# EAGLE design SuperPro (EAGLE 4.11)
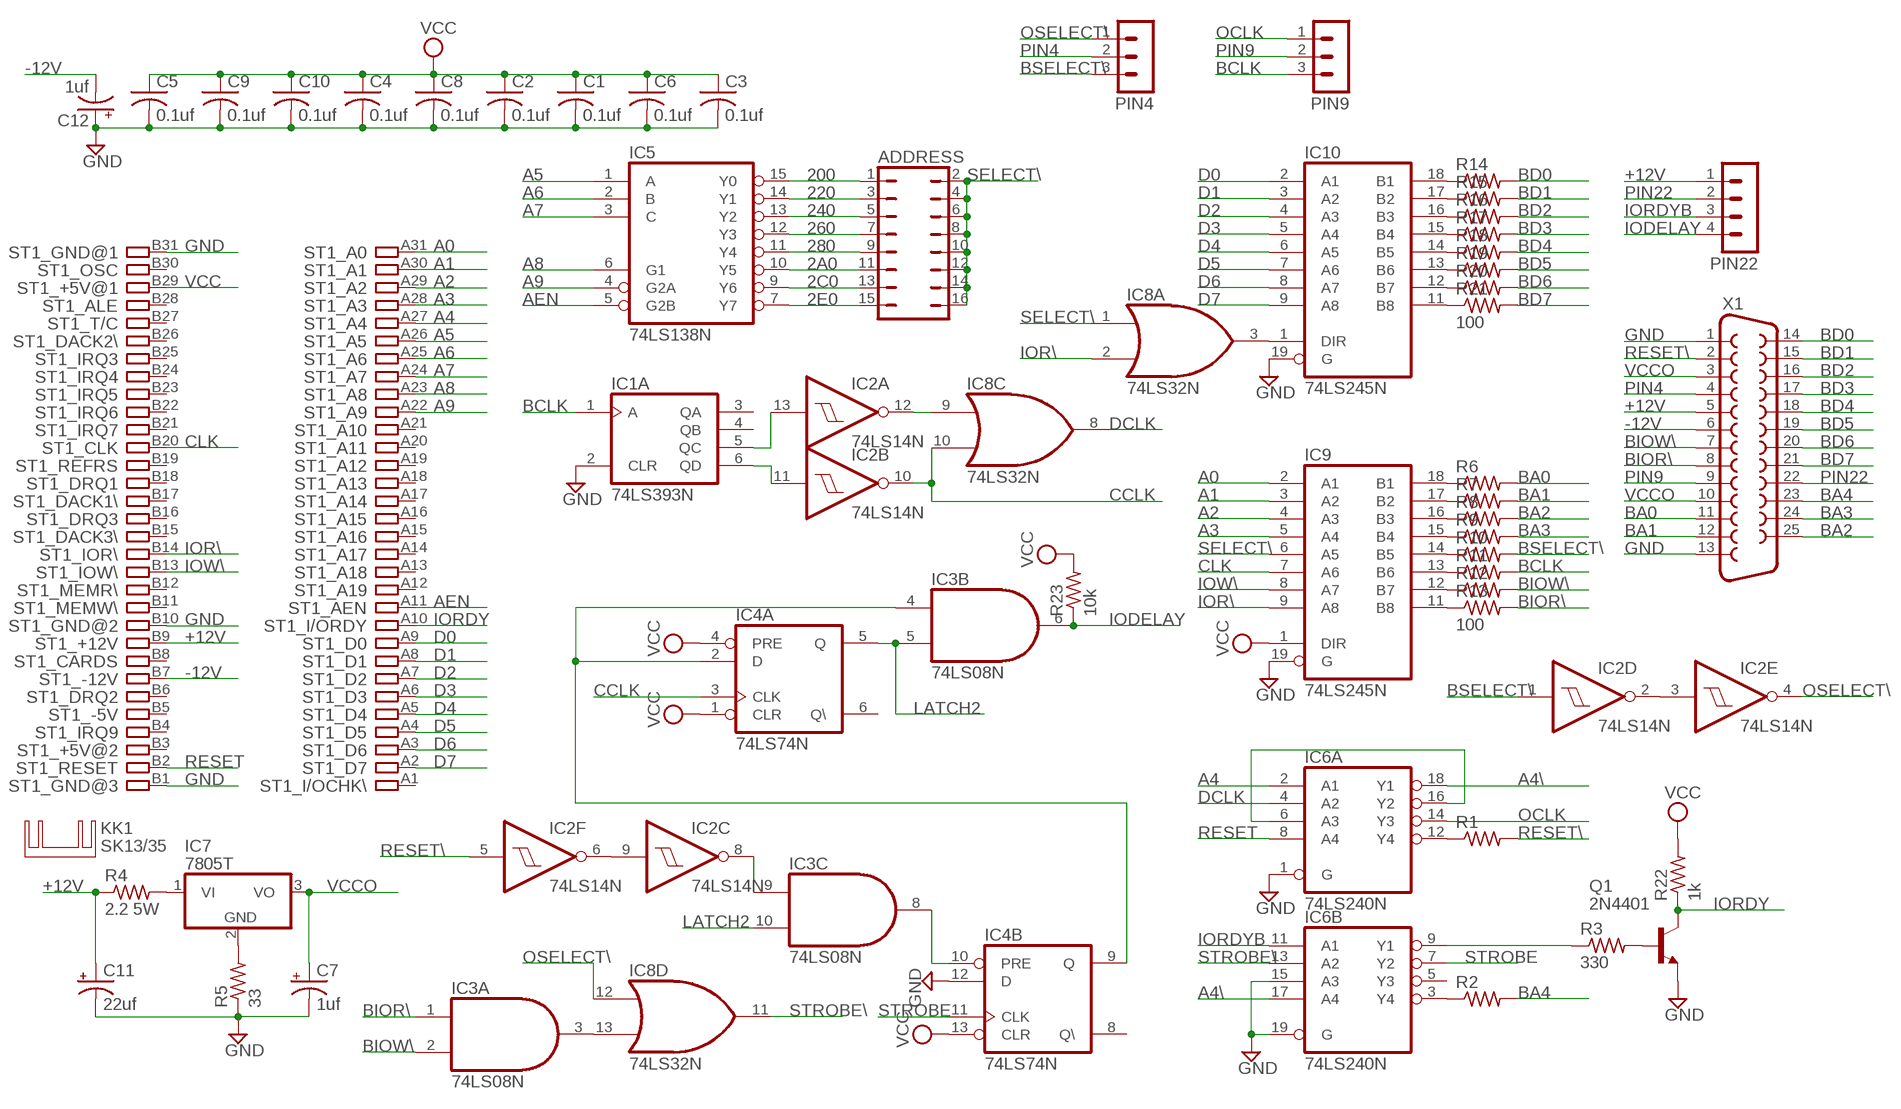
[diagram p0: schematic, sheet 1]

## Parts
ADDRESS  JP8Q  [JP8Q]
C1  0.1uf  C-US050-025X075  [C050-025X075]
C2  0.1uf  C-US050-025X075  [C050-025X075]
C3  0.1uf  C-US050-025X075  [C050-025X075]
C4  0.1uf  C-US050-025X075  [C050-025X075]
C5  0.1uf  C-US050-025X075  [C050-025X075]
C6  0.1uf  C-US050-025X075  [C050-025X075]
C7  1uf  CPOL-USE5-10.5  [E5-10,5]
C8  0.1uf  C-US050-025X075  [C050-025X075]
C9  0.1uf  C-US050-025X075  [C050-025X075]
C10  0.1uf  C-US050-025X075  [C050-025X075]
C11  22uf  CPOL-USE5-10.5  [E5-10,5]
C12  1uf  CPOL-USE5-10.5  [E5-10,5]
IC1  74LS393N  [DIL14]
IC2  74LS14N  [DIL14]
IC3  74LS08N  [DIL14]
IC4  74LS74N  [DIL14]
IC5  74LS138N  [DIL16]
IC6  74LS240N  [DIL20]
IC7  7805T  [TO220H]
IC8  74LS32N  [DIL14]
IC9  74LS245N  [DIL20]
IC10  74LS245N  [DIL20]
KK1  SK13/35  [SK13/35]
PIN4  MA03-1  [MA03-1]
PIN9  MA03-1  [MA03-1]
PIN22  MA04-1  [MA04-1]
Q1  2N4401  2N4416  [TO92]
R1  R-US_0207/10  [0207/10]
R2  R-US_0207/10  [0207/10]
R3  330  R-US_0207/10  [0207/10]
R4  2.2 5W  R-US_0922/22  [0922/22]
R5  33  R-US_0207/10  [0207/10]
R6  R-US_0207/10  [0207/10]
R7  R-US_0207/10  [0207/10]
R8  R-US_0207/10  [0207/10]
R9  R-US_0207/10  [0207/10]
R10  R-US_0207/10  [0207/10]
R11  R-US_0207/10  [0207/10]
R12  R-US_0207/10  [0207/10]
R13  100  R-US_0207/10  [0207/10]
R14  R-US_0207/10  [0207/10]
R15  R-US_0207/10  [0207/10]
R16  R-US_0207/10  [0207/10]
R17  R-US_0207/10  [0207/10]
R18  R-US_0207/10  [0207/10]
R19  R-US_0207/10  [0207/10]
R20  R-US_0207/10  [0207/10]
R21  100  R-US_0207/10  [0207/10]
R22  1k  R-US_0207/10  [0207/10]
R23  10k  R-US_0207/10  [0207/10]
ST1  IBM8BIT  [IBM8BIT]
X1  F25H  [F25H]

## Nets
2A0: ADDRESS.11 IC5.10(Y5)
2C0: ADDRESS.13 IC5.9(Y6)
2E0: ADDRESS.15 IC5.7(Y7)
200: ADDRESS.1 IC5.15(Y0)
220: ADDRESS.3 IC5.14(Y1)
240: ADDRESS.5 IC5.13(Y2)
260: ADDRESS.7 IC5.12(Y3)
280: ADDRESS.9 IC5.11(Y4)
+12V [Power]: C11.+ PIN22.1 R4.1 ST1.B9 X1.5
-12V [Power]: C12.- ST1.B7 X1.6
A0: IC9.2(A1) ST1.A31
A1: IC9.3(A2) ST1.A30
A2: IC9.4(A3) ST1.A29
A3: IC9.5(A4) ST1.A28
A4: IC6.2(A:A1) ST1.A27
A4\: IC6.17(B:A4) IC6.18(A:Y1)
A5: IC5.1(A) ST1.A26
A6: IC5.2(B) ST1.A25
A7: IC5.3(C) ST1.A24
A8: IC5.6(G1) ST1.A23
A9: IC5.4(G2A) ST1.A22
AEN: IC5.5(G2B) ST1.A11
BA0: R6.2 X1.11
BA1: R7.2 X1.12
BA2: R8.2 X1.25
BA3: R9.2 X1.24
BA4: R2.2 X1.23
BCLK: IC1.1(A:A) PIN9.3 R11.2
BD0: R14.2 X1.14
BD1: R15.2 X1.15
BD2: R16.2 X1.16
BD3: R17.2 X1.17
BD4: R18.2 X1.18
BD5: R19.2 X1.19
BD6: R20.2 X1.20
BD7: R21.2 X1.21
BIOR\: IC3.1(A:I0) R13.2 X1.8
BIOW\: IC3.2(A:I1) R12.2 X1.7
BSELECT\: IC2.1(D:I) PIN4.3 R10.2
CCLK: IC2.10(B:O) IC4.3(A:CLK) IC8.10(C:I1)
CLK: IC9.7(A6) ST1.B20
D0: IC10.2(A1) ST1.A9
D1: IC10.3(A2) ST1.A8
D2: IC10.4(A3) ST1.A7
D3: IC10.5(A4) ST1.A6
D4: IC10.6(A5) ST1.A5
D5: IC10.7(A6) ST1.A4
D6: IC10.8(A7) ST1.A3
D7: IC10.9(A8) ST1.A2
DCLK: IC6.4(A:A2) IC8.8(C:O)
GND [Power]: C1.2 C2.2 C3.2 C4.2 C5.2 C6.2 C7.- C8.2 C9.2 C10.2 C11.- C12.+ IC1.2(A:CLR) IC4.12(B:D) IC6.1(A:G) IC6.15(B:A3) IC6.19(B:G) IC9.19(G) IC10.19(G) Q1.3(E) R5.1 ST1.B1 ST1.B10 ST1.B31 X1.1 X1.13
IODELAY: IC3.6(B:O) PIN22.4 R23.1
IOR\: IC8.2(A:I1) IC9.9(A8) ST1.B14
IORDY: Q1.1(C) R22.1 ST1.A10
IORDYB: IC6.11(B:A1) PIN22.3
IOW\: IC9.8(A7) ST1.B13
LATCH2: IC3.5(B:I1) IC3.10(C:I1) IC4.5(A:Q)
N$1: IC8.3(A:O) IC10.1(DIR)
N$2 [Power]: IC7.2(GND) R5.2
N$3: IC10.13(B6) R19.1
N$4: IC10.17(B2) R15.1
N$5: IC10.16(B3) R16.1
N$6: IC10.15(B4) R17.1
N$7: IC10.14(B5) R18.1
N$8: IC10.12(B7) R20.1
N$9: IC10.11(B8) R21.1
N$10: IC10.18(B1) R14.1
N$11: IC9.18(B1) R6.1
N$12: IC9.17(B2) R7.1
N$13: IC9.16(B3) R8.1
N$14: IC9.15(B4) R9.1
N$15: IC9.14(B5) R10.1
N$16: IC9.13(B6) R11.1
N$17: IC9.12(B7) R12.1
N$18: IC9.11(B8) R13.1
N$19: IC6.12(A:Y4) R1.1
N$20: IC2.6(F:O) IC2.9(C:I)
N$21: IC2.2(D:O) IC2.3(E:I)
N$22: IC1.6(A:QD) IC2.11(B:I)
N$23: IC6.3(B:Y4) R2.1
N$24: IC1.5(A:QC) IC2.13(A:I)
N$25 [Power]: IC7.1(VI) R4.2
N$26: IC2.12(A:O) IC8.9(C:I0)
N$28: IC6.6(A:A3) IC6.16(A:Y2)
N$29: IC3.3(A:O) IC8.13(D:I1)
N$30: IC3.4(B:I0) IC4.2(A:D) IC4.9(B:Q)
N$32: IC6.9(B:Y1) R3.1
N$33: IC3.8(C:O) IC4.10(B:PRE)
N$34: IC2.8(C:O) IC3.9(C:I0)
N$37: Q1.2(B) R3.2
OCLK: IC6.14(A:Y3) PIN9.1
OSELECT\: IC2.4(E:O) IC8.12(D:I0) PIN4.1
PIN4: PIN4.2 X1.4
PIN9: PIN9.2 X1.9
PIN22 [Power]: PIN22.2 X1.22
RESET: IC6.8(A:A4) ST1.B2
RESET\: IC2.5(F:I) R1.2 X1.2
SELECT\: ADDRESS.2 ADDRESS.4 ADDRESS.6 ADDRESS.8 ADDRESS.10 ADDRESS.12 ADDRESS.14 ADDRESS.16 IC8.1(A:I0) IC9.6(A5)
STROBE: IC4.11(B:CLK) IC6.7(B:Y2)
STROBE\: IC6.13(B:A2) IC8.11(D:O)
VCC [Power]: C1.1 C2.1 C3.1 C4.1 C5.1 C6.1 C8.1 C9.1 C10.1 IC4.1(A:CLR) IC4.4(A:PRE) IC4.13(B:CLR) IC9.1(DIR) R22.2 R23.2 ST1.B29
VCCO [Power]: C7.+ IC7.3(VO) X1.3 X1.10
Unconnected: IC1.3(A:QA) IC1.4(A:QB) IC1.8(B:QD) IC1.9(B:QC) IC1.10(B:QB) IC1.11(B:QA) IC1.12(B:CLR) IC1.13(B:A) IC3.11(D:O) IC3.12(D:I0) IC3.13(D:I1) IC4.6(A:Q\) IC4.8(B:Q\) IC6.5(B:Y3) IC8.4(B:I0) IC8.5(B:I1) IC8.6(B:O) ST1.A1 ST1.A12 ST1.A13 ST1.A14 ST1.A15 ST1.A16 ST1.A17 ST1.A18 ST1.A19 ST1.A20 ST1.A21 ST1.B3 ST1.B4 ST1.B5 ST1.B6 ST1.B8 ST1.B11 ST1.B12 ST1.B15 ST1.B16 ST1.B17 ST1.B18 ST1.B19 ST1.B21 ST1.B22 ST1.B23 ST1.B24 ST1.B25 ST1.B26 ST1.B27 ST1.B28 ST1.B30

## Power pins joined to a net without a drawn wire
GND: IC1.7(P:GND) IC2.7(P:GND) IC3.7(P:GND) IC4.7(P:GND) IC5.8(GND) IC6.10(P:GND) IC8.7(P:GND) IC9.10(GND) IC10.10(GND)
VCC: IC1.14(P:VCC) IC2.14(P:VCC) IC3.14(P:VCC) IC4.14(P:VCC) IC5.16(VCC) IC6.20(P:VCC) IC8.14(P:VCC) IC9.20(VCC) IC10.20(VCC)

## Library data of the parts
ADDRESS = jumper:JP8Q: JUMPER
C1-C6 C8-C10 = rcl:C-US: CAPACITOR, American symbol
C7 C11 C12 = rcl:CPOL-US: POLARIZED CAPACITOR, American symbol
IC1 = 74xx-us:74*393: Dual 4-bit decade and binary COUNTER
IC2 = 74xx-us:74*14: Hex schmitt trigger INVERTER
IC3 = 74xx-us:74*08: Quad 2-input AND gate
IC4 = 74xx-us:74*74: Dual D type positive edge triggered FLIP FLOP, preset and clear
IC5 = 74xx-us:74*138: 3-line to 8-line DECODER/DEMULTIPLEXER
IC6 = 74xx-us:74*240: Octal BUFFER and LINE DRIVER, 3-state
IC7 = linear:78*: Positive VOLTAGE REGULATOR
IC8 = 74xx-us:74*32: Quad 2-input OR gate
IC9 IC10 = 74xx-us:74*245: Octal BUS TRANSCEIVER, 3-state
KK1 = heatsink:SK13/35: HEATSINK
PIN4 PIN9 = con-lstb:MA03-1: PIN HEADER
PIN22 = con-lstb:MA04-1: PIN HEADER
Q1 = transistor-npn:2N4416: NPN Transistor
R1-R23 = rcl:R-US_: RESISTOR, American symbol
ST1 = con-pc:IBM8BIT: 8-bit CARD IBM/PC-AT
X1 = con-subd:F25: SUB-D

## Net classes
1 Power: width 0.762 mm, drill 0.254 mm

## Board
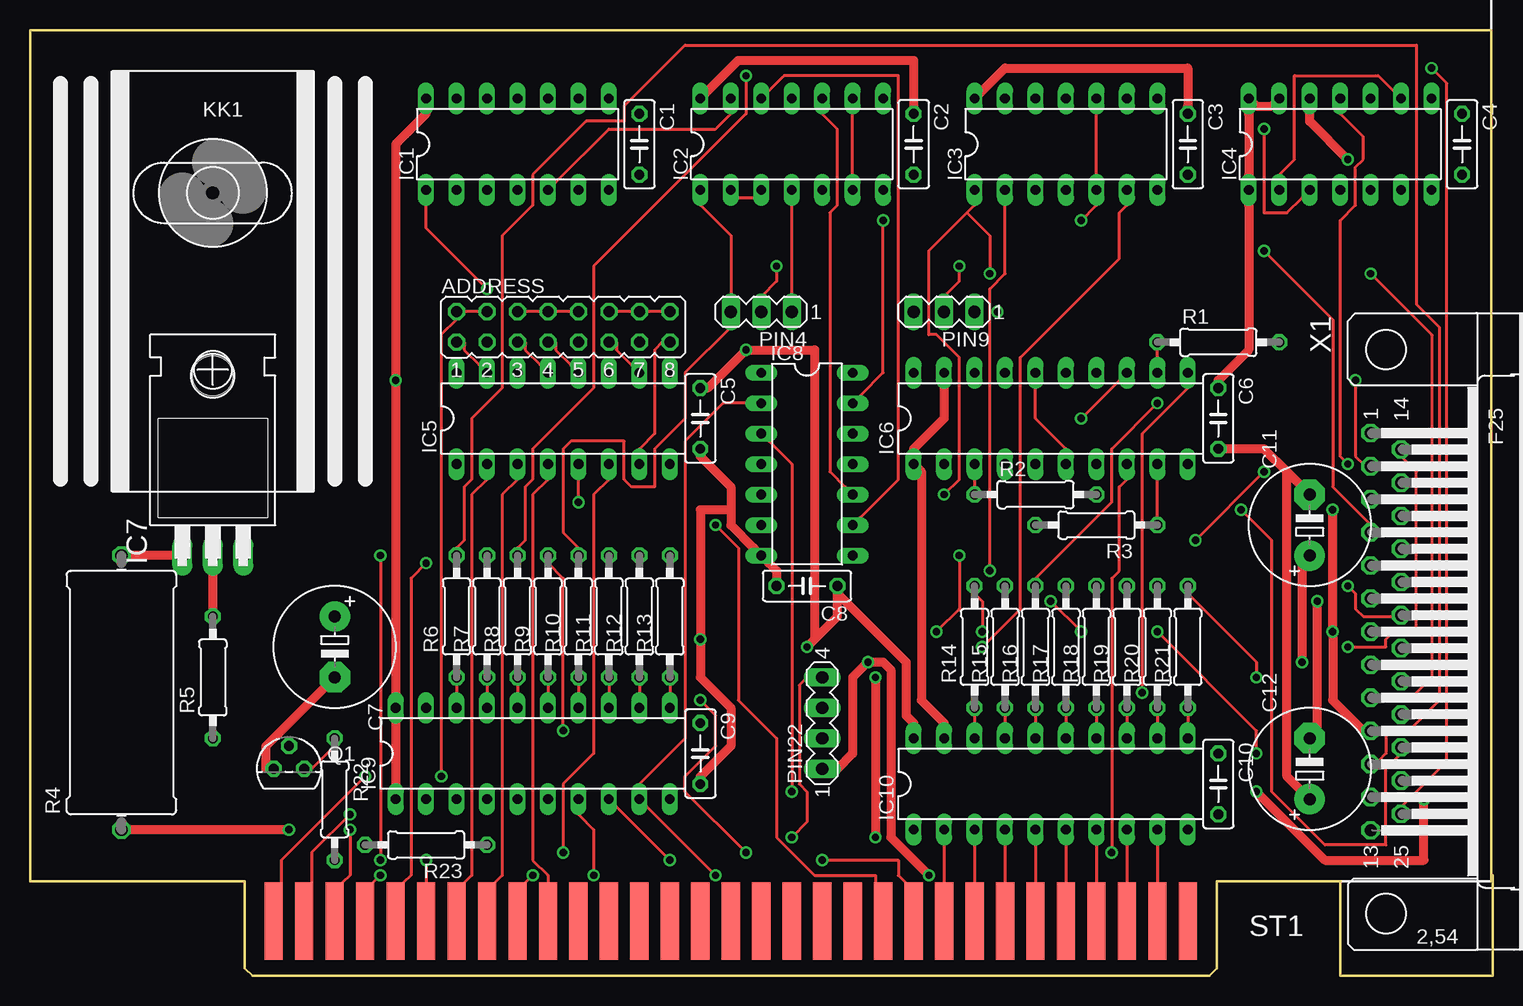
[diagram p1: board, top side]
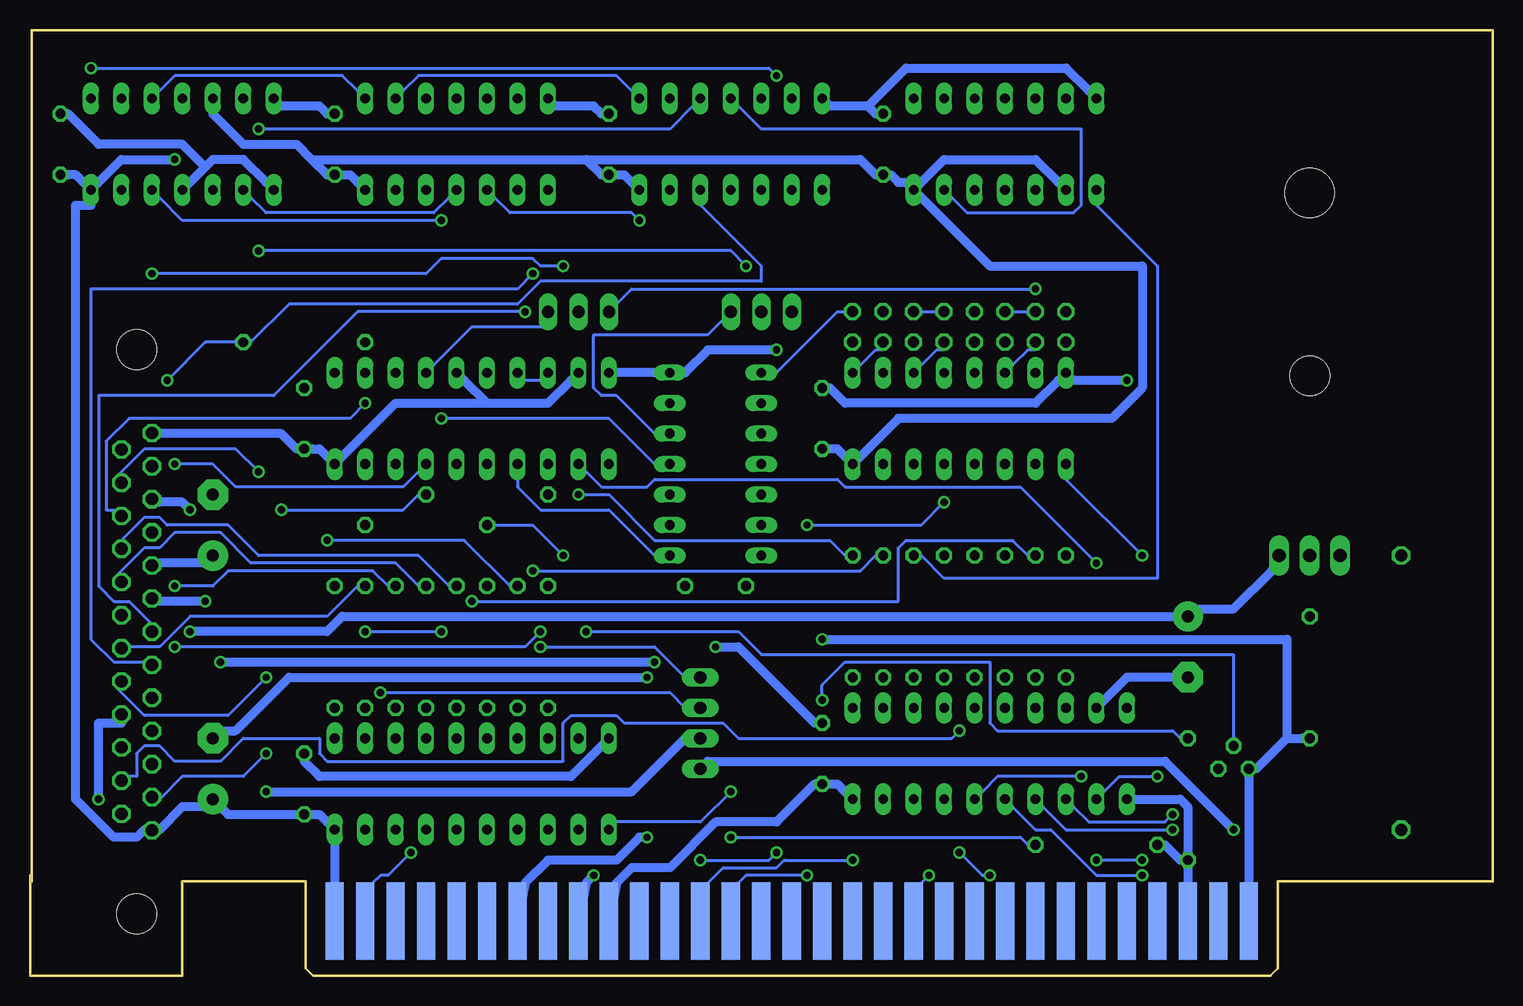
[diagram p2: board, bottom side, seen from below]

Size 121.92 x 78.87 mm. Coordinates in mm from the lower left corner, seen from the top.
Outline: 121.79,7.87 121.79,78.87 0,78.87 0,7.87 17.91,7.87 17.91,0.64 18.54,0 97.79,0 98.3,0 98.93,0.64 98.93,7.87 109.22,7.87 109.22,0 121.92,0 121.92,8.38
Copper layers (1*16): Top 0.035mm / dielectric 1.5mm / Bottom 0.035mm
Design rules "olimex10mil": minimum track width 10mil, minimum drill 24mil, track to track 10mil, track to pad 10mil, pad to pad 10mil, via to via 10mil, smd to smd 10mil, copper to edge 40mil, drill to drill 10mil, minimum pad ring 10mil, minimum via ring 8mil, stop-mask expansion 0mil, vias tented up to drill 0mil, thermal gap 10mil

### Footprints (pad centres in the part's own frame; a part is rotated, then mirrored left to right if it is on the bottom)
JP8Q = drill 0.914 octagon: 1 -8.89,-1.27; 2 -8.89,1.27; 3 -6.35,-1.27; 4 -6.35,1.27; 5 -3.81,-1.27; 6 -3.81,1.27; 7 -1.27,-1.27; 8 -1.27,1.27; 9 1.27,-1.27; 10 1.27,1.27; 11 3.81,-1.27; 12 3.81,1.27; 13 6.35,-1.27; 14 6.35,1.27; 15 8.89,-1.27; 16 8.89,1.27
C050-025X075 = drill 0.813 octagon: 1 -2.54,0; 2 2.54,0
E5-10,5 = drill 1.016 pad 2.54 round: + -2.54,0 | drill 1.016 pad 2.54 octagon: - 2.54,0
DIL14 = drill 0.813 long: 1 -7.62,-3.81; 2 -5.08,-3.81; 3 -2.54,-3.81; 4 0,-3.81; 5 2.54,-3.81; 6 5.08,-3.81; 7 7.62,-3.81; 8 7.62,3.81; 9 5.08,3.81; 10 2.54,3.81; 11 0,3.81; 12 -2.54,3.81; 13 -5.08,3.81; 14 -7.62,3.81
DIL16 = drill 0.813 long: 1 -8.89,-3.81; 2 -6.35,-3.81; 3 -3.81,-3.81; 4 -1.27,-3.81; 5 1.27,-3.81; 6 3.81,-3.81; 7 6.35,-3.81; 8 8.89,-3.81; 9 8.89,3.81; 10 6.35,3.81; 11 3.81,3.81; 12 1.27,3.81; 13 -1.27,3.81; 14 -3.81,3.81; 15 -6.35,3.81; 16 -8.89,3.81
DIL20 = drill 0.813 long: 1 -11.43,-3.81; 2 -8.89,-3.81; 3 -6.35,-3.81; 4 -3.81,-3.81; 5 -1.27,-3.81; 6 1.27,-3.81; 7 3.81,-3.81; 8 6.35,-3.81; 9 8.89,-3.81; 10 11.43,-3.81; 11 11.43,3.81; 12 8.89,3.81; 13 6.35,3.81; 14 3.81,3.81; 15 1.27,3.81; 16 -1.27,3.81; 17 -3.81,3.81; 18 -6.35,3.81; 19 -8.89,3.81; 20 -11.43,3.81
TO220H = drill 1.118 long: 1 -2.54,-10.16; 2 0,-10.16; 3 2.54,-10.16 | hole 3.302: 0,4.826
MA03-1 = drill 1.016 long: 1 -2.54,0; 2 0,0; 3 2.54,0
MA04-1 = drill 1.016 long: 1 -3.81,0; 2 -1.27,0; 3 1.27,0; 4 3.81,0
TO92 = drill 0.813 octagon: 1 1.27,0; 2 0,1.905; 3 -1.27,0
0207/10 = drill 0.813 octagon: 1 -5.08,0; 2 5.08,0
0922/22 = drill 1.016 octagon: 1 -11.43,0; 2 11.43,0
IBM8BIT = smd 1.524 x 6.477: A1 -25.4,5.08; A2 -27.94,5.08; A3 -30.48,5.08; A4 -33.02,5.08; A5 -35.56,5.08; A6 -38.1,5.08; A7 -40.64,5.08; A8 -43.18,5.08; A9 -45.72,5.08; A10 -48.26,5.08; A11 -50.8,5.08; A12 -53.34,5.08; A13 -55.88,5.08; A14 -58.42,5.08; A15 -60.96,5.08; A16 -63.5,5.08; A17 -66.04,5.08; A18 -68.58,5.08; A19 -71.12,5.08; A20 -73.66,5.08; A21 -76.2,5.08; A22 -78.74,5.08; A23 -81.28,5.08; A24 -83.82,5.08; A25 -86.36,5.08; A26 -88.9,5.08; A27 -91.44,5.08; A28 -93.98,5.08; A29 -96.52,5.08; A30 -99.06,5.08; A31 -101.6,5.08 | smd 1.524 x 6.477 bottom: B1 -25.4,5.08; B2 -27.94,5.08; B3 -30.48,5.08; B4 -33.02,5.08; B5 -35.56,5.08; B6 -38.1,5.08; B7 -40.64,5.08; B8 -43.18,5.08; B9 -45.72,5.08; B10 -48.26,5.08; B11 -50.8,5.08; B12 -53.34,5.08; B13 -55.88,5.08; B14 -58.42,5.08; B15 -60.96,5.08; B16 -63.5,5.08; B17 -66.04,5.08; B18 -68.58,5.08; B19 -71.12,5.08; B20 -73.66,5.08; B21 -76.2,5.08; B22 -78.74,5.08; B23 -81.28,5.08; B24 -83.82,5.08; B25 -86.36,5.08; B26 -88.9,5.08; B27 -91.44,5.08; B28 -93.98,5.08; B29 -96.52,5.08; B30 -99.06,5.08; B31 -101.6,5.08
4,1 = hole 4.1: 0,0
F25H = drill 1.016 octagon: 1 -16.561,-1.27; 2 -13.792,-1.27; 3 -11.049,-1.27; 4 -8.28,-1.27; 5 -5.512,-1.27; 6 -2.769,-1.27; 7 0,-1.27; 8 2.769,-1.27; 9 5.512,-1.27; 10 8.28,-1.27; 11 11.049,-1.27; 12 13.792,-1.27; 13 16.561,-1.27; 14 -15.189,1.27; 15 -12.421,1.27; 16 -9.652,1.27; 17 -6.909,1.27; 18 -4.14,1.27; 19 -1.372,1.27; 20 1.372,1.27; 21 4.14,1.27; 22 6.909,1.27; 23 9.652,1.27; 24 12.421,1.27; 25 15.189,1.27 | hole 3.302: -23.52,0; 23.52,0

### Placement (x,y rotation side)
ADDRESS  44.45,54.1 0 top
C1  50.8,69.34 270 top
C2  73.66,69.34 270 top
C3  96.52,69.34 270 top
C4  119.38,69.34 270 top
C5  55.88,46.48 270 top
C6  99.06,46.48 270 top
C7  25.4,27.43 270 top
C8  64.77,32.51 180 top
C9  55.88,18.54 270 top
C10  99.06,16 270 top
C11  106.68,37.59 90 top
C12  106.68,17.27 90 top
IC1  40.64,69.34 0 top
IC2  63.5,69.34 0 top
IC3  86.36,69.34 0 top
IC4  109.22,69.34 0 top
IC5  44.45,46.48 0 top
IC6  85.09,46.48 0 top
IC7  15.24,45.21 0 top
IC8  64.77,42.67 270 top
IC9  41.91,18.54 0 top
IC10  85.09,16 0 top
KK1  15.24,61.72 90 top
PIN4  60.96,55.37 180 top
PIN9  76.2,55.37 180 top
PIN22  66.04,21.08 90 top
Q1  21.59,17.27 0 top
R1  99.06,52.83 0 top
R2  83.82,40.13 0 top
R3  88.9,37.59 180 top
R4  7.62,23.62 90 top
R5  15.24,24.89 90 top
R6  35.56,29.97 90 top
R7  38.1,29.97 90 top
R8  40.64,29.97 90 top
R9  43.18,29.97 90 top
R10  45.72,29.97 90 top
R11  48.26,29.97 90 top
R12  50.8,29.97 90 top
R13  53.34,29.97 90 top
R14  78.74,27.43 90 top
R15  81.28,27.43 90 top
R16  83.82,27.43 90 top
R17  86.36,27.43 90 top
R18  88.9,27.43 90 top
R19  91.44,27.43 90 top
R20  93.98,27.43 90 top
R21  96.52,27.43 90 top
R22  25.4,14.73 270 top
R23  33.02,10.92 180 top
ST1  121.92,-0.51 0 top
U$1  [4,1]  15.24,65.28 0 top
X1  113.03,28.7 270 top

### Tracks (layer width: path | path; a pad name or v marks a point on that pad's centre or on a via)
2A0
  Top 0.254: IC5.10 50.17,50.93 48.89,52.2 48.89,52.83 ADDRESS.11
2C0
  Bottom 0.254: IC5.9 52.7,50.93 51.44,52.2 50.8,52.2 ADDRESS.13
2E0
  Top 0.254: IC5.7 50.8,43.94 52.07,45.21 52.07,52.2 52.7,52.83 ADDRESS.15
200
  Top 0.254: IC5.15 37.47,50.93 36.2,52.2 36.2,52.83 ADDRESS.1
220
  Bottom 0.254: IC5.14 40,50.93 38.73,52.2 38.1,52.2 ADDRESS.3
240
  Top 0.254: IC5.13 42.55,50.93 41.28,52.2 41.28,52.83 ADDRESS.5
260
  Top 0.254: IC5.12 45.09,50.93 43.81,52.2 43.81,52.83 ADDRESS.7
280
  Bottom 0.254: IC5.11 47.62,50.93 46.36,52.2 45.72,52.2 ADDRESS.9
+12V  (via drill 0.61)
  Top 0.762: v21.59,12.19 8.25,12.19 R4.1 | v106.05,26.16 106.05,34.42 C11.+ | PIN22.1 67.31,17.27 68.58,18.54 68.58,24.89 v69.85,26.16 71.12,26.16 71.75,25.53 71.75,11.56 v74.93,8.38
  Bottom 0.762: X1.5 111.12,34.42 107.31,34.42 C11.+ | v21.59,12.19 27.31,17.91 65.41,17.91 PIN22.1 | v106.05,26.16 v69.85,26.16 | v74.93,8.38 75.56,7.75 ST1.B9
-12V  (via drill 0.61)
  Top 0.762: v107.31,31.24 107.31,20.45 C12.- | v70.48,24.89 v70.48,11.56
  Bottom 0.762: v107.31,31.24 111.12,31.24 X1.6 | v70.48,11.56 71.12,11.56 73.03,9.65 78.74,9.65 80.65,7.75 ST1.B7 | v70.48,24.89 100.33,24.89 104.78,20.45 106.05,20.45 C12.-
A0  (via drill 0.61)
  Top 0.254: v27.94,16.64 20.95,9.65 20.95,7.75 ST1.A31
  Bottom 0.254: v27.94,16.64 31.11,16.64 32.39,15.37 IC9.2
A1  (via drill 0.61)
  Top 0.254: v26.67,13.46 23.5,10.29 23.5,7.75 ST1.A30
  Bottom 0.254: v26.67,13.46 27.31,12.83 33.66,12.83 34.92,14.1 IC9.3
A2  (via drill 0.61)
  Top 0.254: v26.67,12.19 26.67,8.38 26.03,7.75 ST1.A29
  Bottom 0.254: v26.67,12.19 35.56,12.19 37.47,14.1 IC9.4
A3  (via drill 0.61)
  Top 0.254: v29.21,8.38 28.58,7.75 ST1.A28
  Bottom 0.254: v29.21,8.38 33.02,8.38 36.83,12.19 38.1,12.19 40,14.1 IC9.5
A4  (via drill 0.61)
  Top 0.254: v33.02,34.42 31.75,33.15 31.75,8.38 31.11,7.75 ST1.A27
  Bottom 0.254: v33.02,34.42 39.37,40.77 53.98,40.77 54.61,41.4 69.85,41.4 70.48,40.77 74.3,40.77 75.56,42.04 IC6.2
A4\
  Bottom 0.254: IC6.18 79.38,49.66 80.65,49.66 IC6.17
A5  (via drill 0.61)
  Top 0.254: v29.21,35.05 v29.21,9.65 | v33.02,9.65 33.02,7.75 ST1.A26
  Bottom 0.254: v29.21,35.05 35.56,41.4 IC5.1 | v29.21,9.65 v33.02,9.65
A6
  Top 0.254: IC5.2 38.1,41.4 36.83,40.13 36.83,8.38 36.2,7.75 ST1.A25
A7
  Top 0.254: IC5.3 40.64,41.4 39.37,40.13 39.37,8.38 38.73,7.75 ST1.A24
A8  (via drill 0.61)
  Top 0.254: v44.45,10.29 44.45,16 46.99,18.54 46.99,40.13 48.26,41.4 IC5.6 | v41.91,8.38 41.28,7.75 ST1.A23
  Bottom 0.254: v44.45,10.29 42.55,8.38 v41.91,8.38
A9
  Top 0.254: IC5.4 43.18,41.4 41.91,40.13 41.91,9.65 43.18,8.38 43.18,7.75 ST1.A22
AEN  (via drill 0.61)
  Top 0.254: v45.72,39.5 45.72,41.4 IC5.5 | v57.15,37.59 59.05,35.69 59.05,22.99 62.23,19.81 62.23,11.56 65.41,8.38 70.48,8.38 70.48,7.75 ST1.A11
  Bottom 0.254: v45.72,39.5 47.62,37.59 v57.15,37.59
BA0
  Top 0.254: R6.2 35.56,35.69 36.2,36.32 36.2,40.77 36.83,41.4 36.83,46.48 39.37,49.02 39.37,61.72 41.91,64.26 41.91,66.8 46.36,71.25 49.53,71.25 49.53,72.52 54.61,77.6 115.57,77.6 115.57,56.01 117.47,54.1 117.47,22.99 114.94,20.45 113.03,20.45 113.03,18.54 112.39,17.91 X1.11
BA1  (via drill 0.61)
  Top 0.254: v87.63,28.7 v85.09,31.24 | v93.98,28.7 102.23,20.45 v102.23,18.54
  Bottom 0.254: v85.09,31.24 49.53,31.24 49.53,35.69 48.89,36.32 40,36.32 38.73,35.05 R7.2 | v93.98,28.7 v87.63,28.7 | v102.23,18.54 104.14,16.64 109.22,16.64 111.12,14.73 X1.12
BA2  (via drill 0.61)
  Top 0.254: v59.69,75.06 59.69,71.88 46.99,59.18 46.99,49.02 41.91,43.94 41.91,41.4 41.28,40.77 41.28,36.32 40.64,35.69 R8.2 | v116.84,75.69 118.11,74.42 118.11,17.91 114.3,14.1 X1.25
  Bottom 0.254: v59.69,75.06 60.33,75.69 v116.84,75.69
BA3  (via drill 0.61)
  Top 0.254: v44.45,20.45 44.45,33.15 43.18,34.42 R9.2
  Bottom 0.254: v44.45,20.45 45.09,19.81 62.87,19.81 64.14,21.08 72.39,21.08 73.03,21.72 76.84,21.72 77.47,21.08 77.47,17.91 97.16,17.91 97.79,18.54 97.79,19.81 104.14,19.81 106.05,17.91 109.86,17.91 111.12,19.18 112.39,19.18 113.03,18.54 113.03,16.64 113.67,16.64 X1.24
BA4  (via drill 0.61)
  Top 0.254: v100.97,38.86 103.5,36.32 103.5,15.37 107.95,10.92 113.03,10.92 113.03,17.27 114.3,18.54 X1.23
  Bottom 0.254: v100.97,38.86 90.81,38.86 89.53,40.13 R2.2
BCLK  (via drill 0.61)
  Top 0.254: v38.1,57.28 33.02,62.36 33.02,64.26 IC1.1
  Bottom 0.254: IC1.1 33.02,64.26 27.94,59.18 27.94,33.15 45.72,33.15 47.62,35.05 R11.2 | v38.1,57.28 71.75,57.28 73.03,56.01 PIN9.3
BD0  (via drill 0.61)
  Top 0.254: v79.38,28.7 79.38,31.24 78.74,31.88 R14.2 | v109.86,27.43 113.03,27.43 113.03,28.07 113.67,28.7 115.57,28.7 115.57,42.04 114.3,43.31 X1.14
  Bottom 0.254: v79.38,28.7 80.65,27.43 v109.86,27.43
BD1  (via drill 0.61)
  Top 0.254: v97.16,36.32 v102.87,42.04
  Bottom 0.254: v97.16,36.32 85.72,36.32 81.91,32.51 R15.2 | v102.87,42.04 104.78,43.94 112.39,43.94 114.94,41.4 X1.15
BD2  (via drill 0.61)
  Top 0.254: v93.98,47.75 90.17,43.94 90.17,39.5 83.82,33.15 R16.2
  Bottom 0.254: v93.98,47.75 95.25,46.48 113.67,46.48 115.57,44.58 115.57,38.86 114.3,38.86 X1.16
BD3
  Bottom 0.254: R17.2 87,32.51 89.53,35.05 102.87,35.05 105.41,37.59 110.49,37.59 111.12,38.23 112.39,38.23 114.3,36.32 X1.17
BD4
  Bottom 0.254: R18.2 89.53,32.51 91.44,34.42 103.5,34.42 106.05,36.96 109.86,36.96 111.12,35.69 112.39,35.69 114.94,33.15 X1.18
BD5  (via drill 0.61)
  Top 0.254: v109.86,32.51 110.49,31.88 110.49,30.61 111.12,29.97 113.67,29.97 X1.19
  Bottom 0.254: v109.86,32.51 106.68,32.51 105.41,33.78 93.34,33.78 92.08,32.51 R19.2
BD6
  Bottom 0.254: R20.2 94.62,32.51 97.16,29.97 108.59,29.97 111.12,27.43 113.67,27.43 X1.20
BD7  (via drill 0.61)
  Top 0.254: v102.23,24.89 102.23,26.16 96.52,31.88 R21.2
  Bottom 0.254: v102.23,24.89 105.41,21.72 112.39,21.72 114.94,24.26 X1.21
BIOR\  (via drill 0.61)
  Top 0.254: v76.2,40.13 77.47,41.4 77.47,51.56 75.56,53.47 74.93,53.47 74.93,60.45 78.11,63.63 | 78.11,63.63 78.74,64.26 IC3.1 | v80.01,58.55 80.01,61.72 78.11,63.63
  Bottom 0.254: v76.2,40.13 73.66,40.13 69.85,36.32 55.25,36.32 53.98,35.05 R13.2 | v80.01,58.55 81.28,57.28 116.84,57.28 116.84,28.07 114.94,26.16 112.39,26.16 X1.8
BIOW\  (via drill 0.61)
  Top 0.254: 80.01,55.37 80.01,57.28 81.28,58.55 81.28,64.26 IC3.2 | v80.01,33.78 80.01,55.37 | 80.01,55.37 v80.65,55.37
  Bottom 0.254: v80.01,33.78 52.7,33.78 51.44,35.05 R12.2 | v80.65,55.37 94.62,55.37 101.6,48.39 116.2,48.39 116.2,32.51 114.94,31.24 113.67,31.24 111.76,29.34 X1.7
BSELECT\
  Top 0.254: R10.2 45.72,35.69 44.45,36.96 44.45,43.94 45.09,44.58 49.53,44.58 49.53,41.4 50.17,40.77 52.07,40.77 52.07,43.94 54.61,46.48 54.61,50.29 58.42,54.1 PIN4.3 58.42,56.64 58.42,61.72 55.88,64.26 IC2.1
CCLK  (via drill 0.61)
  Top 0.254: IC8.10 67.94,40.77 66.68,42.04 66.68,63.63 67.31,64.26 67.31,70.61 66.04,71.88 IC2.10 | v102.87,70.61 102.87,63.63 104.78,63.63 106.05,64.9 IC4.3
  Bottom 0.254: v102.87,70.61 68.58,70.61 66.68,72.52 IC2.10
CLK  (via drill 0.61)
  Top 0.254: v46.99,8.38 46.99,12.19 45.72,13.46 IC9.7
  Bottom 0.254: v46.99,8.38 47.62,7.75 ST1.B20
D0
  Top 0.254: IC10.2 76.2,10.92 76.2,7.75 ST1.A9
D1
  Top 0.254: IC10.3 78.74,10.92 78.74,7.75 ST1.A8
D2
  Top 0.254: IC10.4 81.28,10.92 81.28,7.75 ST1.A7
D3
  Top 0.254: IC10.5 83.82,10.92 83.82,7.75 ST1.A6
D4
  Top 0.254: IC10.6 86.36,10.92 86.36,7.75 ST1.A5
D5
  Top 0.254: IC10.7 88.9,10.92 88.9,7.75 ST1.A4
D6
  Top 0.254: IC10.8 91.44,10.92 91.44,7.75 ST1.A3
D7
  Top 0.254: IC10.9 93.98,10.92 93.98,7.75 ST1.A2
DCLK
  Bottom 0.254: IC8.8 69.85,35.05 73.66,38.86 79.38,38.86 81.28,40.77 81.28,41.4 IC6.4
GND  (via drill 0.61)
  Top 0.762: C7.- 24.77,24.26 19.69,19.18 19.69,17.27 Q1.3 | C8.2 62.23,33.15 62.23,33.78 61.59,34.42 IC8.7 60.33,35.69 58.42,37.59 58.42,38.86 | 58.42,38.86 58.42,40.77 55.88,43.31 C5.2 | 58.42,38.86 55.88,38.86 v55.88,28.07 55.88,24.89 58.42,22.35 58.42,19.18 55.88,16.64 C9.2 | 104.78,42.04 102.87,43.94 99.69,43.94 C6.2 | 104.78,42.04 106.05,40.77 C11.- | IC6.19 76.2,49.02 76.2,46.48 73.66,43.94 IC6.1 74.3,42.04 74.3,22.99 76.2,21.08 IC10.19 | 104.78,42.04 104.78,16.64 106.05,15.37 C12.+ | v109.86,68.07 106.68,71.25 106.68,71.88 IC4.12
  Bottom 0.762: IC9.19 32.39,22.99 30.48,24.89 26.03,24.89 C7.- | 17.14,19.81 19.69,17.27 Q1.3 20.32,16.64 20.32,7.75 ST1.B31 | 17.14,19.81 15.88,19.81 R5.1 | C5.2 55.25,43.94 54.61,43.94 53.98,43.31 IC5.8 52.7,43.31 49.53,46.48 31.75,46.48 29.21,49.02 29.21,59.18 41.91,59.18 47.62,64.9 IC1.7 | IC9.10 53.98,15.37 54.61,16 55.25,16 C9.2 56.52,16 59.69,12.83 64.77,12.83 68.58,9.02 71.75,9.02 73.03,7.75 ST1.B10 | 17.14,19.81 17.14,28.07 v55.88,28.07 | ST1.B1 96.52,7.75 96.52,10.92 IC10.10 97.16,12.83 97.79,13.46 98.42,13.46 C10.2 99.69,13.46 105.41,13.46 106.05,14.1 C12.+ 107.31,14.1 109.22,14.1 111.12,12.19 X1.13 112.39,12.19 113.03,11.56 114.94,11.56 118.11,14.73 118.11,64.26 116.84,64.26 IC4.7 | X1.1 111.12,45.21 100.97,45.21 99.69,43.94 C6.2 98.42,43.94 97.79,43.94 97.16,43.31 IC6.10 95.89,43.31 91.44,47.75 83.82,47.75 | 83.82,47.75 85.72,49.66 IC6.15 | 83.82,47.75 78.74,47.75 76.84,49.66 IC6.19 | IC1.2 36.2,66.17 38.1,68.07 45.72,68.07 47.62,66.17 IC1.7 | IC1.7 48.89,66.17 49.53,66.17 50.17,66.8 C1.2 51.44,66.8 52.7,68.07 75.56,68.07 | IC4.7 117.47,66.17 118.11,66.8 118.75,66.8 C4.2 | IC2.7 71.75,66.17 72.39,66.8 73.03,66.8 C2.2 74.3,66.8 75.56,68.07 | IC3.7 94.62,66.17 95.25,66.8 95.89,66.8 C3.2 97.16,66.8 98.42,68.07 | 98.42,68.07 99.69,69.34 104.14,69.34 106.68,71.88 IC4.12 | 98.42,68.07 75.56,68.07 | v109.86,68.07 114.3,68.07 116.2,66.17 IC4.7
IODELAY  (via drill 0.61)
  Top 0.254: v63.5,11.56 64.77,12.83 64.77,15.37 64.14,16 64.14,24.26 64.77,24.89 PIN22.4 | v79.38,27.43 82.55,30.61 82.55,51.56 90.81,59.82 90.81,63.63 91.44,64.26 IC3.6
  Bottom 0.254: v63.5,11.56 39.37,11.56 38.73,10.92 R23.1 | v79.38,27.43 69.85,27.43 67.31,24.89 PIN22.4
IOR\  (via drill 0.61)
  Top 0.254: IC8.2 59.69,47.75 57.78,47.75 54.61,44.58 54.61,19.81 50.8,16 IC9.9 51.44,14.1 v57.15,8.38
  Bottom 0.254: v57.15,8.38 62.23,8.38 62.87,7.75 ST1.B14
IORDY  (via drill 0.61)
  Top 0.254: Q1.1 23.5,17.27 25.4,19.18 R22.1 | v55.88,22.99 57.15,21.72 57.15,19.18 54.61,16.64 54.61,15.37 v59.69,10.29 | v66.04,9.65 72.39,9.65 72.39,8.38 73.03,7.75 ST1.A10
  Bottom 0.254: v55.88,22.99 55.88,24.26 53.98,26.16 41.91,26.16 41.91,21.08 41.28,20.45 26.67,20.45 26.03,19.81 R22.1 | v59.69,10.29 60.33,9.65 v66.04,9.65
IORDYB  (via drill 0.61)
  Top 0.254: v92.71,23.62 92.71,45.21 96.52,49.02 IC6.11
  Bottom 0.254: v92.71,23.62 68.58,23.62 67.31,22.35 PIN22.3
IOW\  (via drill 0.61)
  Top 0.254: v53.34,9.65 48.89,14.1 IC9.8
  Bottom 0.254: v53.34,9.65 59.05,9.65 59.69,9.02 64.14,9.02 65.41,7.75 ST1.B13
LATCH2  (via drill 0.61)
  Top 0.254: IC3.10 88.9,71.88 88.9,66.8 IC3.5 88.9,64.26 v87.63,62.99
  Bottom 0.254: v87.63,62.99 109.22,62.99 111.12,64.9 IC4.5
N$1  (via drill 0.61)
  Top 0.254: v63.5,15.37 63.5,42.67 61.59,44.58 IC8.3
  Bottom 0.254: v63.5,15.37 66.04,12.83 73.03,12.83 IC10.1
N$2
  Top 0.762: R5.2 15.24,30.61 15.24,33.78 IC7.2
N$3
  Top 0.254: IC10.13 91.44,21.08 91.44,21.72 R19.1
N$4
  Top 0.254: IC10.17 81.28,21.08 81.28,21.72 R15.1
N$5
  Top 0.254: IC10.16 83.82,21.08 83.82,21.72 R16.1
N$6
  Top 0.254: IC10.15 86.36,21.08 86.36,21.72 R17.1
N$7
  Top 0.254: IC10.14 88.9,21.08 88.9,21.72 R18.1
N$8
  Top 0.254: IC10.12 93.98,21.08 93.98,21.72 R20.1
N$9
  Top 0.254: IC10.11 96.52,21.08 96.52,21.72 R21.1
N$10
  Top 0.254: IC10.18 78.74,21.08 78.74,21.72 R14.1
N$11
  Top 0.254: IC9.18 35.56,23.62 35.56,24.26 R6.1
N$12
  Top 0.254: IC9.17 38.1,23.62 38.1,24.26 R7.1
N$13
  Top 0.254: IC9.16 40.64,23.62 40.64,24.26 R8.1
N$14
  Top 0.254: IC9.15 43.18,23.62 43.18,24.26 R9.1
N$15
  Top 0.254: IC9.14 45.72,23.62 45.72,24.26 R10.1
N$16
  Top 0.254: IC9.13 48.26,23.62 48.26,24.26 R11.1
N$17
  Top 0.254: IC9.12 50.8,23.62 50.8,24.26 R12.1
N$18
  Top 0.254: IC9.11 53.34,23.62 53.34,24.26 R13.1
N$19
  Top 0.254: IC6.12 93.98,51.56 93.98,52.2 R1.1
N$20
  Top 0.254: IC2.6 68.58,66.8 68.58,71.88 IC2.9
N$21
  Top 0.254: IC2.2 59.05,64.9 60.33,64.9 IC2.3
N$22
  Bottom 0.254: IC1.6 45.09,64.9 43.81,63.63 34.92,63.63 34.29,64.26 34.29,70.61 60.96,70.61 62.87,72.52 IC2.11
N$23
  Top 0.254: R2.1 78.74,40.77 78.74,41.4 IC6.3
N$24
  Top 0.254: IC1.5 43.81,66.17 48.26,70.61 57.15,70.61 58.42,71.88 IC2.13
N$25
  Top 0.762: R4.2 8.25,35.05 12.06,35.05 IC7.1
N$26
  Top 0.254: IC2.12 61.59,73.79 62.87,75.06 72.39,75.06 72.39,41.4 69.22,38.23 IC8.9
N$28
  Top 0.254: IC6.6 86.36,43.94 83.82,46.48 83.82,49.02 IC6.16
N$29  (via drill 0.61)
  Top 0.254: v71.12,62.99 71.12,50.29 69.22,48.39 IC8.13
  Bottom 0.254: v71.12,62.99 71.75,63.63 81.91,63.63 83.19,64.9 IC3.3
N$30
  Top 0.254: IC4.9 113.67,73.79 112.39,75.06 105.41,75.06 105.41,68.07 104.14,66.8 IC4.2
  Bottom 0.254: IC3.4 87,64.9 88.27,63.63 102.23,63.63 103.5,64.9 IC4.2
N$32
  Top 0.254: R3.1 93.98,38.23 93.98,41.4 IC6.9
N$33
  Bottom 0.254: IC3.8 94.62,73.79 95.89,75.06 109.86,75.06 111.12,73.79 IC4.10
N$34
  Bottom 0.254: IC2.8 71.75,73.79 73.03,75.06 89.53,75.06 90.81,73.79 IC3.9
N$37  (via drill 0.61)
  Top 0.254: v75.56,28.7 77.47,30.61 v77.47,35.05
  Bottom 0.254: v75.56,28.7 62.87,28.7 60.96,26.8 21.59,26.8 21.59,19.81 Q1.2 | v77.47,35.05 80.01,37.59 83.19,37.59 R3.2
OCLK
  Bottom 0.254: IC6.14 88.27,50.93 85.09,54.1 78.74,54.1 PIN9.1
OSELECT\
  Top 0.254: IC2.4 63.5,64.26 63.5,56.64 PIN4.1
  Bottom 0.254: IC8.12 69.85,45.21 73.03,48.39 74.3,48.39 74.93,49.02 74.93,53.47 65.41,53.47 64.14,54.74 PIN4.1
PIN4  (via drill 0.61)
  Top 0.254: v62.23,59.18 62.23,57.91 60.96,56.64 PIN4.2 | v102.87,60.45 108.59,54.74 108.59,40.77 111.76,37.59 X1.4
  Bottom 0.254: v62.23,59.18 63.5,60.45 v102.87,60.45
PIN9  (via drill 0.61)
  Top 0.254: v77.47,59.18 77.47,57.91 76.2,56.64 PIN9.2 | v111.76,58.55 116.84,53.47 116.84,24.89 114.94,22.99 112.39,22.99 X1.9
  Bottom 0.254: v77.47,59.18 79.38,59.18 80.01,59.82 87.63,59.82 88.9,58.55 v111.76,58.55
PIN22  (via drill 0.61)
  Top 0.762: v102.23,15.37 107.95,9.65 116.2,9.65 v116.2,14.73
  Bottom 0.762: v102.23,15.37 71.75,15.37 67.31,19.81 PIN22.2 | v116.2,14.73 116.2,21.08 114.3,21.08 X1.22
RESET  (via drill 0.61)
  Top 0.254: v90.17,10.29 90.17,33.15 90.81,33.78 90.81,40.77 91.44,41.4 IC6.8
  Bottom 0.254: v90.17,10.29 92.08,8.38 92.71,8.38 93.34,7.75 ST1.B2
RESET\  (via drill 0.61)
  Top 0.254: v110.49,49.66 110.49,43.31 111.12,42.67 X1.2
  Bottom 0.254: IC2.5 66.04,64.26 60.96,59.18 60.96,57.91 79.38,57.91 81.28,56.01 100.33,56.01 103.5,52.83 R1.2 104.78,52.83 107.31,52.83 v110.49,49.66
SELECT\  (via drill 0.61)
  Top 0.254: v34.29,16.64 34.29,53.47 35.56,54.74 ADDRESS.2 36.2,55.37 37.47,55.37 ADDRESS.4 | ADDRESS.6 41.28,55.37 42.55,55.37 ADDRESS.8 43.81,55.37 45.09,55.37 ADDRESS.10 | ADDRESS.12 48.89,55.37 50.17,55.37 ADDRESS.14 51.44,55.37 52.7,55.37 ADDRESS.16
  Bottom 0.254: IC8.1 59.69,50.29 54.61,55.37 53.98,55.37 ADDRESS.16 | v34.29,16.64 41.28,16.64 42.55,15.37 IC9.6 | ADDRESS.6 40,55.37 38.73,55.37 ADDRESS.4 | ADDRESS.12 47.62,55.37 46.36,55.37 ADDRESS.10
STROBE  (via drill 0.61)
  Top 0.254: v109.86,42.67 109.22,43.31 109.22,62.99 110.49,64.26 110.49,67.44 111.12,68.07 111.12,69.98 109.22,71.88 IC4.11
  Bottom 0.254: v109.86,42.67 106.68,42.67 104.78,40.77 90.81,40.77 89.53,42.04 IC6.7
STROBE\  (via drill 0.61)
  Top 0.254: v87.63,46.48 90.81,49.66 IC6.13
  Bottom 0.254: v87.63,46.48 73.66,46.48 69.85,42.67 IC8.11
VCC  (via drill 0.61)
  Top 0.762: C5.1 56.52,49.02 v59.69,52.2 65.41,52.2 65.41,28.07 | 65.41,28.07 67.31,29.97 67.31,31.88 | 65.41,28.07 v64.77,27.43 | 67.31,31.88 C8.1 67.31,31.88 | 67.31,31.88 73.03,26.16 73.03,21.72 73.66,21.08 IC10.20 | C6.1 99.06,49.66 101.6,52.2 101.6,64.26 IC4.1 101.6,66.8 101.6,71.88 IC4.14 102.23,72.52 103.5,72.52 IC4.13 | IC9.1 30.48,16 30.48,21.08 IC9.20 30.48,23.62 v30.48,49.66 30.48,69.34 33.02,71.88 IC1.14 | IC3.14 79.38,73.79 81.28,75.69 96.52,75.69 96.52,72.52 C3.1 | IC2.14 56.52,73.79 59.05,76.33 73.66,76.33 73.66,72.52 C2.1
  Bottom 0.762: IC6.20 73.03,50.29 69.85,50.29 IC8.14 67.31,50.29 65.41,52.2 v59.69,52.2 | C5.1 55.25,49.02 53.98,47.75 38.1,47.75 36.2,49.66 IC5.16 34.92,49.66 v30.48,49.66 | v64.77,27.43 62.87,27.43 56.52,21.08 C9.1 | C10.1 99.06,17.91 97.79,16.64 76.84,16.64 74.3,19.18 IC10.20 | 107.31,67.44 106.68,68.07 104.14,68.07 102.23,66.17 IC4.1 | 107.31,67.44 108.59,66.17 IC4.4 | 107.31,67.44 109.22,69.34 116.2,69.34 118.75,71.88 C4.1 | R22.2 25.4,9.02 25.4,7.75 ST1.B29 | R23.2 27.31,10.92 26.03,9.65 R22.2 | IC9.1 29.84,14.73 26.03,14.73 25.4,14.1 25.4,10.29 R22.2 | 52.07,72.52 51.44,71.88 C1.1 | 52.07,72.52 55.25,72.52 IC2.14 | 52.07,72.52 48.89,75.69 35.56,75.69 33.66,73.79 IC1.14 | C2.1 74.3,71.88 74.93,72.52 78.11,72.52 IC3.14 | C3.1 97.16,71.88 97.79,72.52 100.97,72.52 IC4.14
VCCO  (via drill 0.61)
  Top 0.762: v108.59,38.86 v108.59,28.7 108.59,22.99 111.12,20.45 X1.10
  Bottom 0.762: IC7.3 18.42,33.78 21.59,30.61 24.77,30.61 C7.+ 26.03,29.97 95.89,29.97 97.16,28.7 v108.59,28.7 | v108.59,38.86 109.22,39.5 111.12,39.5 X1.3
